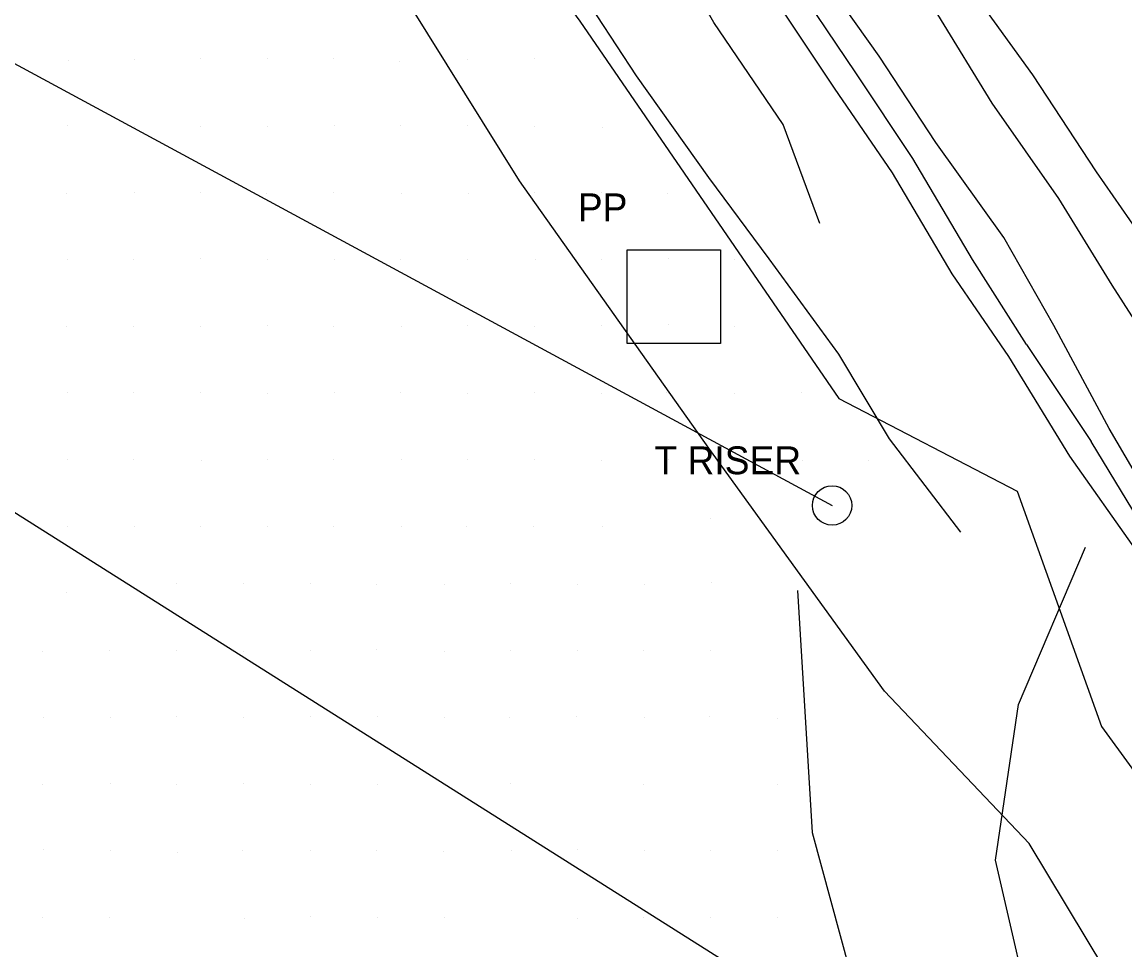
# Model space of a CAD drawing. Extents: x 1602514 to 1609837, y 863887 to 871157.
# Drawn here: x 1604592.6 to 1604840.4, y 867560.7 to 867769.2 of the extents above; entities that cross this region are included whole.
import ezdxf

# ---------------------------------------------------------------- set-up
doc = ezdxf.new("R2010")
doc.units = 0
for name, color, linetype in [('Survey-Flow line', 7, 'Continuous'), ('Survey-Ridge Lines', 7, 'Continuous'), ('Survey-Spot dirt', 7, 'Continuous'), ('Survey-Vegetation trees', 7, 'Continuous'), ('Text General Notes', 7, 'Continuous'), ('Utility-Pole', 7, 'Continuous'), ('Utility-Telephone', 7, 'Continuous')]:
    doc.layers.add(name, color=color, linetype=linetype)

msp = doc.modelspace()

# ---------------------------------------------------------------- linework, layer by layer
at = {"layer": 'Survey-Flow line'}
msp.add_line((1604818.28, 867696.73), (1604832.8, 867674.97), dxfattribs=at)
msp.add_line((1604818.28, 867696.73), (1604832.8, 867674.97), dxfattribs=at)
for points in [[(1604818.28, 867696.73), (1604806.16, 867715.81), (1604792.77, 867738.49), (1604779.99, 867757.77), (1604764.6, 867780.55), (1604750.71, 867800.58)], [(1604818.28, 867696.73), (1604806.16, 867715.81), (1604792.77, 867738.49), (1604779.99, 867757.77), (1604764.6, 867780.55), (1604750.71, 867800.58)], [(1604921.51, 867529.19), (1604914.06, 867533.2), (1604906.06, 867537.4), (1604903.35, 867541.31), (1604892.31, 867564.09), (1604882.35, 867587.62), (1604870.6, 867609.9), (1604857.3, 867633.58), (1604846.26, 867652.84), (1604832.8, 867674.97)], [(1604921.51, 867529.19), (1604914.06, 867533.2), (1604906.06, 867537.4), (1604903.35, 867541.31), (1604892.31, 867564.09), (1604882.35, 867587.62), (1604870.6, 867609.9), (1604857.3, 867633.58), (1604846.26, 867652.84), (1604832.8, 867674.97)], [(1604825.24, 867194.65), (1604821.17, 867216.57), (1604817.74, 867236.45), (1604799.75, 867259.61), (1604775.29, 867293.59), (1604776.33, 867315.88), (1604792.23, 867342.57), (1604806.9, 867375.02), (1604822.2, 867411.61), (1604827.76, 867442.51), (1604835.8, 867478.97), (1604831.81, 867504.07), (1604821.12, 867538.37), (1604811.33, 867580.91), (1604816.48, 867615.89), (1604831.53, 867651.16)], [(1604825.24, 867194.65), (1604821.17, 867216.57), (1604817.74, 867236.45), (1604799.75, 867259.61), (1604775.29, 867293.59), (1604776.33, 867315.88), (1604792.23, 867342.57), (1604806.9, 867375.02), (1604822.2, 867411.61), (1604827.76, 867442.51), (1604835.8, 867478.97), (1604831.81, 867504.07), (1604821.12, 867538.37), (1604811.33, 867580.91), (1604816.48, 867615.89), (1604831.53, 867651.16)]]:
    msp.add_lwpolyline(points, dxfattribs=at)
at = {"layer": 'Survey-Ridge Lines'}
for points in [[(1604803.53, 867654.54), (1604787.54, 867675.54), (1604776.14, 867694.56), (1604760.52, 867715.97), (1604746.92, 867734.21), (1604730.69, 867757.04), (1604717.43, 867777.35), (1604704.53, 867801.09), (1604688.27, 867817.96), (1604670.81, 867837.65), (1604656.79, 867858.81), (1604645.82, 867885.21), (1604624.86, 867905.16)], [(1604803.53, 867654.54), (1604787.54, 867675.54), (1604776.14, 867694.56), (1604760.52, 867715.97), (1604746.92, 867734.21), (1604730.69, 867757.04), (1604717.43, 867777.35), (1604704.53, 867801.09), (1604688.27, 867817.96), (1604670.81, 867837.65), (1604656.79, 867858.81), (1604645.82, 867885.21), (1604624.86, 867905.16)], [(1604771.85, 867723.88), (1604763.63, 867746.12), (1604748.04, 867769.06), (1604736.02, 867790.32), (1604718.51, 867810.68), (1604705.34, 867829.88)], [(1604771.85, 867723.88), (1604763.63, 867746.12), (1604748.04, 867769.06), (1604736.02, 867790.32), (1604718.51, 867810.68), (1604705.34, 867829.88)], [(1604906.22, 867543.32), (1604898.1, 867568.13), (1604886.72, 867590.67), (1604873.69, 867612.06), (1604860.94, 867636.07), (1604850.01, 867655.49), (1604836.9, 867677.83), (1604824.43, 867700.97), (1604813.19, 867720.78), (1604797.9, 867742.06), (1604785.17, 867761.46), (1604769.36, 867783.85), (1604755.21, 867803.72), (1604740.2, 867825.57)], [(1604906.22, 867543.32), (1604898.1, 867568.13), (1604886.72, 867590.67), (1604873.69, 867612.06), (1604860.94, 867636.07), (1604850.01, 867655.49), (1604836.9, 867677.83), (1604824.43, 867700.97), (1604813.19, 867720.78), (1604797.9, 867742.06), (1604785.17, 867761.46), (1604769.36, 867783.85), (1604755.21, 867803.72), (1604740.2, 867825.57)], [(1604900.26, 867539.16), (1604885.57, 867559.39), (1604876.38, 867583.45), (1604866.26, 867606.87), (1604853.93, 867631.28), (1604842.96, 867650.52), (1604828.06, 867671.66), (1604814.35, 867694.02), (1604801.58, 867712.56), (1604788.16, 867735.27), (1604775.15, 867754.32), (1604759.9, 867777.29), (1604746.08, 867797.34), (1604731.41, 867817.99)], [(1604900.26, 867539.16), (1604885.57, 867559.39), (1604876.38, 867583.45), (1604866.26, 867606.87), (1604853.93, 867631.28), (1604842.96, 867650.52), (1604828.06, 867671.66), (1604814.35, 867694.02), (1604801.58, 867712.56), (1604788.16, 867735.27), (1604775.15, 867754.32), (1604759.9, 867777.29), (1604746.08, 867797.34), (1604731.41, 867817.99)], [(1604901.44, 867631.43), (1604888.34, 867654.79), (1604875.92, 867673.73), (1604861.71, 867695.15), (1604847.12, 867716.62), (1604834.01, 867735.51), (1604819.72, 867757.3), (1604806.03, 867776.32)], [(1604901.44, 867631.43), (1604888.34, 867654.79), (1604875.92, 867673.73), (1604861.71, 867695.15), (1604847.12, 867716.62), (1604834.01, 867735.51), (1604819.72, 867757.3), (1604806.03, 867776.32)], [(1604935.81, 867563.97), (1604921.11, 867584.19), (1604904.08, 867602.79), (1604892.04, 867624.87), (1604879.36, 867648.66), (1604868.18, 867668.28), (1604851.65, 867688.13), (1604837.55, 867710.02), (1604825.58, 867729.54), (1604810.61, 867750.94), (1604798.36, 867770.86)], [(1604935.81, 867563.97), (1604921.11, 867584.19), (1604904.08, 867602.79), (1604892.04, 867624.87), (1604879.36, 867648.66), (1604868.18, 867668.28), (1604851.65, 867688.13), (1604837.55, 867710.02), (1604825.58, 867729.54), (1604810.61, 867750.94), (1604798.36, 867770.86)], [(1604766.88, 867641.49), (1604770.15, 867587.13), (1604782.72, 867540.86), (1604800.31, 867482.58)], [(1604766.88, 867641.49), (1604770.15, 867587.13), (1604782.72, 867540.86), (1604800.31, 867482.58)]]:
    msp.add_lwpolyline(points, dxfattribs=at)
at = {"layer": 'Survey-Spot dirt'}
for p, q in [((1604603.11, 867760.42), (1604603.11, 867760.42)), ((1604603.11, 867760.42), (1604603.11, 867760.42)), ((1604617.8, 867760.77), (1604617.8, 867760.77)), ((1604617.8, 867760.77), (1604617.8, 867760.77)), ((1604632.74, 867760.9), (1604632.74, 867760.9)), ((1604632.74, 867760.9), (1604632.74, 867760.9)), ((1604647.66, 867760.98), (1604647.66, 867760.98)), ((1604647.66, 867760.98), (1604647.66, 867760.98)), ((1604662.51, 867760.93), (1604662.51, 867760.93)), ((1604662.51, 867760.93), (1604662.51, 867760.93)), ((1604677.33, 867760.32), (1604677.33, 867760.32)), ((1604677.33, 867760.32), (1604677.33, 867760.32)), ((1604692.81, 867760.8), (1604692.81, 867760.8)), ((1604692.81, 867760.8), (1604692.81, 867760.8)), ((1604707.83, 867760.98), (1604707.83, 867760.98)), ((1604707.83, 867760.98), (1604707.83, 867760.98)), ((1604722.63, 867760.72), (1604722.63, 867760.72)), ((1604722.63, 867760.72), (1604722.63, 867760.72)), ((1604602.88, 867745.89), (1604602.88, 867745.89)), ((1604602.88, 867745.89), (1604602.88, 867745.89)), ((1604617.82, 867745.71), (1604617.82, 867745.71)), ((1604617.82, 867745.71), (1604617.82, 867745.71)), ((1604632.73, 867745.66), (1604632.73, 867745.66)), ((1604632.73, 867745.66), (1604632.73, 867745.66)), ((1604647.68, 867745.7), (1604647.68, 867745.7)), ((1604647.68, 867745.7), (1604647.68, 867745.7)), ((1604662.78, 867745.89), (1604662.78, 867745.89)), ((1604662.78, 867745.89), (1604662.78, 867745.89)), ((1604677.63, 867745.83), (1604677.63, 867745.83)), ((1604677.63, 867745.83), (1604677.63, 867745.83)), ((1604692.65, 867745.84), (1604692.65, 867745.84)), ((1604692.65, 867745.84), (1604692.65, 867745.84)), ((1604707.76, 867745.78), (1604707.76, 867745.78)), ((1604707.76, 867745.78), (1604707.76, 867745.78)), ((1604723.03, 867745.54), (1604723.03, 867745.54)), ((1604723.03, 867745.54), (1604723.03, 867745.54)), ((1604602.7, 867730.75), (1604602.7, 867730.75)), ((1604602.7, 867730.75), (1604602.7, 867730.75)), ((1604617.85, 867730.94), (1604617.85, 867730.94)), ((1604617.85, 867730.94), (1604617.85, 867730.94)), ((1604632.77, 867730.91), (1604632.77, 867730.91)), ((1604632.77, 867730.91), (1604632.77, 867730.91)), ((1604647.52, 867730.57), (1604647.52, 867730.57)), ((1604647.52, 867730.57), (1604647.52, 867730.57)), ((1604662.71, 867730.97), (1604662.71, 867730.97)), ((1604662.71, 867730.97), (1604662.71, 867730.97)), ((1604677.81, 867730.73), (1604677.81, 867730.73)), ((1604677.81, 867730.73), (1604677.81, 867730.73)), ((1604692.93, 867730.67), (1604692.93, 867730.67)), ((1604692.93, 867730.67), (1604692.93, 867730.67)), ((1604707.71, 867730.88), (1604707.71, 867730.88)), ((1604707.71, 867730.88), (1604707.71, 867730.88)), ((1604722.89, 867730.85), (1604722.89, 867730.85)), ((1604722.89, 867730.85), (1604722.89, 867730.85)), ((1604737.7, 867730.74), (1604737.7, 867730.74)), ((1604737.7, 867730.74), (1604737.7, 867730.74)), ((1604602.85, 867715.72), (1604602.85, 867715.72)), ((1604602.85, 867715.72), (1604602.85, 867715.72)), ((1604617.72, 867715.77), (1604617.72, 867715.77)), ((1604617.72, 867715.77), (1604617.72, 867715.77)), ((1604632.66, 867715.95), (1604632.66, 867715.95)), ((1604632.66, 867715.95), (1604632.66, 867715.95)), ((1604647.67, 867715.82), (1604647.67, 867715.82)), ((1604647.67, 867715.82), (1604647.67, 867715.82)), ((1604662.91, 867715.73), (1604662.91, 867715.73)), ((1604662.91, 867715.73), (1604662.91, 867715.73)), ((1604677.65, 867715.92), (1604677.65, 867715.92)), ((1604677.65, 867715.92), (1604677.65, 867715.92)), ((1604692.8, 867715.8), (1604692.8, 867715.8)), ((1604692.8, 867715.8), (1604692.8, 867715.8)), ((1604708.03, 867715.74), (1604708.03, 867715.74)), ((1604708.03, 867715.74), (1604708.03, 867715.74)), ((1604722.81, 867715.84), (1604722.81, 867715.84)), ((1604722.81, 867715.84), (1604722.81, 867715.84)), ((1604737.76, 867715.96), (1604737.76, 867715.96)), ((1604737.76, 867715.96), (1604737.76, 867715.96)), ((1604752.78, 867715.79), (1604752.78, 867715.79)), ((1604752.78, 867715.79), (1604752.78, 867715.79)), ((1604602.63, 867700.85), (1604602.63, 867700.85)), ((1604602.63, 867700.85), (1604602.63, 867700.85)), ((1604617.69, 867700.84), (1604617.69, 867700.84)), ((1604617.69, 867700.84), (1604617.69, 867700.84)), ((1604632.71, 867700.74), (1604632.71, 867700.74)), ((1604632.71, 867700.74), (1604632.71, 867700.74)), ((1604647.68, 867700.91), (1604647.68, 867700.91)), ((1604647.68, 867700.91), (1604647.68, 867700.91)), ((1604662.65, 867700.77), (1604662.65, 867700.77)), ((1604662.65, 867700.77), (1604662.65, 867700.77)), ((1604677.92, 867700.68), (1604677.92, 867700.68)), ((1604677.92, 867700.68), (1604677.92, 867700.68)), ((1604692.7, 867700.88), (1604692.7, 867700.88)), ((1604692.7, 867700.88), (1604692.7, 867700.88)), ((1604707.76, 867700.72), (1604707.76, 867700.72)), ((1604707.76, 867700.72), (1604707.76, 867700.72)), ((1604722.79, 867700.95), (1604722.79, 867700.95)), ((1604722.79, 867700.95), (1604722.79, 867700.95)), ((1604737.86, 867701.18), (1604737.86, 867701.18)), ((1604737.86, 867701.18), (1604737.86, 867701.18)), ((1604752.65, 867700.71), (1604752.65, 867700.71)), ((1604752.65, 867700.71), (1604752.65, 867700.71)), ((1604602.79, 867685.91), (1604602.79, 867685.91)), ((1604602.79, 867685.91), (1604602.79, 867685.91)), ((1604617.65, 867685.83), (1604617.65, 867685.83)), ((1604617.65, 867685.83), (1604617.65, 867685.83)), ((1604632.62, 867685.87), (1604632.62, 867685.87)), ((1604632.62, 867685.87), (1604632.62, 867685.87)), ((1604647.72, 867685.8), (1604647.72, 867685.8)), ((1604647.72, 867685.8), (1604647.72, 867685.8)), ((1604662.89, 867685.87), (1604662.89, 867685.87)), ((1604662.89, 867685.87), (1604662.89, 867685.87)), ((1604677.69, 867685.88), (1604677.69, 867685.88)), ((1604677.69, 867685.88), (1604677.69, 867685.88)), ((1604692.79, 867685.81), (1604692.79, 867685.81)), ((1604692.79, 867685.81), (1604692.79, 867685.81)), ((1604707.68, 867685.85), (1604707.68, 867685.85)), ((1604707.68, 867685.85), (1604707.68, 867685.85)), ((1604722.87, 867685.71), (1604722.87, 867685.71)), ((1604722.87, 867685.71), (1604722.87, 867685.71)), ((1604737.5, 867685.9), (1604737.5, 867685.9)), ((1604737.5, 867685.9), (1604737.5, 867685.9)), ((1604752.78, 867685.81), (1604752.78, 867685.81)), ((1604752.78, 867685.81), (1604752.78, 867685.81)), ((1604767.71, 867685.86), (1604767.71, 867685.86)), ((1604767.71, 867685.86), (1604767.71, 867685.86)), ((1604602.74, 867670.79), (1604602.74, 867670.79)), ((1604602.74, 867670.79), (1604602.74, 867670.79)), ((1604617.73, 867670.91), (1604617.73, 867670.91)), ((1604617.73, 867670.91), (1604617.73, 867670.91)), ((1604632.89, 867670.74), (1604632.89, 867670.74)), ((1604632.89, 867670.74), (1604632.89, 867670.74)), ((1604647.71, 867670.88), (1604647.71, 867670.88)), ((1604647.71, 867670.88), (1604647.71, 867670.88)), ((1604662.71, 867670.86), (1604662.71, 867670.86)), ((1604662.71, 867670.86), (1604662.71, 867670.86)), ((1604677.78, 867670.98), (1604677.78, 867670.98)), ((1604677.78, 867670.98), (1604677.78, 867670.98)), ((1604692.75, 867670.95), (1604692.75, 867670.95)), ((1604692.75, 867670.95), (1604692.75, 867670.95)), ((1604707.7, 867670.91), (1604707.7, 867670.91)), ((1604707.7, 867670.91), (1604707.7, 867670.91)), ((1604722.82, 867670.74), (1604722.82, 867670.74)), ((1604722.82, 867670.74), (1604722.82, 867670.74)), ((1604737.91, 867670.85), (1604737.91, 867670.85)), ((1604737.91, 867670.85), (1604737.91, 867670.85)), ((1604752.69, 867670.89), (1604752.69, 867670.89)), ((1604752.69, 867670.89), (1604752.69, 867670.89)), ((1604767.89, 867670.77), (1604767.89, 867670.77)), ((1604767.89, 867670.77), (1604767.89, 867670.77)), ((1604782.75, 867670.76), (1604782.75, 867670.76)), ((1604782.75, 867670.76), (1604782.75, 867670.76)), ((1604602.81, 867655.74), (1604602.81, 867655.74)), ((1604602.81, 867655.74), (1604602.81, 867655.74)), ((1604617.87, 867655.75), (1604617.87, 867655.75)), ((1604617.87, 867655.75), (1604617.87, 867655.75)), ((1604632.73, 867655.84), (1604632.73, 867655.84)), ((1604632.73, 867655.84), (1604632.73, 867655.84)), ((1604647.72, 867655.86), (1604647.72, 867655.86)), ((1604647.72, 867655.86), (1604647.72, 867655.86)), ((1604662.69, 867655.84), (1604662.69, 867655.84)), ((1604662.69, 867655.84), (1604662.69, 867655.84)), ((1604677.83, 867655.92), (1604677.83, 867655.92)), ((1604677.83, 867655.92), (1604677.83, 867655.92)), ((1604692.58, 867655.84), (1604692.58, 867655.84)), ((1604692.58, 867655.84), (1604692.58, 867655.84)), ((1604707.64, 867655.77), (1604707.64, 867655.77)), ((1604707.64, 867655.77), (1604707.64, 867655.77)), ((1604723.01, 867655.94), (1604723.01, 867655.94)), ((1604723.01, 867655.94), (1604723.01, 867655.94)), ((1604747.33, 867657.74), (1604747.33, 867657.74)), ((1604747.33, 867657.74), (1604747.33, 867657.74)), ((1604747.52, 867643.21), (1604747.52, 867643.21)), ((1604747.52, 867643.21), (1604747.52, 867643.21)), ((1604602.67, 867641.04), (1604602.67, 867641.04)), ((1604602.67, 867641.04), (1604602.67, 867641.04)), ((1604627.34, 867642.97), (1604627.34, 867642.97)), ((1604627.34, 867642.97), (1604627.34, 867642.97)), ((1604642.28, 867643.05), (1604642.28, 867643.05)), ((1604642.28, 867643.05), (1604642.28, 867643.05)), ((1604657.36, 867642.98), (1604657.36, 867642.98)), ((1604657.36, 867642.98), (1604657.36, 867642.98)), ((1604672.17, 867642.92), (1604672.17, 867642.92)), ((1604672.17, 867642.92), (1604672.17, 867642.92)), ((1604687.57, 867642.88), (1604687.57, 867642.88)), ((1604687.57, 867642.88), (1604687.57, 867642.88)), ((1604702.29, 867643.03), (1604702.29, 867643.03)), ((1604702.29, 867643.03), (1604702.29, 867643.03)), ((1604717.32, 867642.86), (1604717.32, 867642.86)), ((1604717.32, 867642.86), (1604717.32, 867642.86)), ((1604732.44, 867642.87), (1604732.44, 867642.87)), ((1604732.44, 867642.87), (1604732.44, 867642.87)), ((1604597.32, 867627.81), (1604597.32, 867627.81)), ((1604597.32, 867627.81), (1604597.32, 867627.81)), ((1604612.36, 867627.96), (1604612.36, 867627.96)), ((1604612.36, 867627.96), (1604612.36, 867627.96)), ((1604627.37, 867628.08), (1604627.37, 867628.08)), ((1604627.37, 867628.08), (1604627.37, 867628.08)), ((1604642.36, 867627.76), (1604642.36, 867627.76)), ((1604642.36, 867627.76), (1604642.36, 867627.76)), ((1604657.36, 867628), (1604657.36, 867628)), ((1604657.36, 867628), (1604657.36, 867628)), ((1604672.34, 867628.12), (1604672.34, 867628.12)), ((1604672.34, 867628.12), (1604672.34, 867628.12)), ((1604687.47, 867627.86), (1604687.47, 867627.86)), ((1604687.47, 867627.86), (1604687.47, 867627.86)), ((1604702.35, 867628), (1604702.35, 867628)), ((1604702.35, 867628), (1604702.35, 867628)), ((1604717.31, 867628.04), (1604717.31, 867628.04)), ((1604717.31, 867628.04), (1604717.31, 867628.04)), ((1604732.33, 867627.93), (1604732.33, 867627.93)), ((1604732.33, 867627.93), (1604732.33, 867627.93)), ((1604747.22, 867627.91), (1604747.22, 867627.91)), ((1604747.22, 867627.91), (1604747.22, 867627.91)), ((1604597.42, 867613.04), (1604597.42, 867613.04)), ((1604597.42, 867613.04), (1604597.42, 867613.04)), ((1604612.52, 867612.88), (1604612.52, 867612.88)), ((1604612.52, 867612.88), (1604612.52, 867612.88)), ((1604627.31, 867613.09), (1604627.31, 867613.09)), ((1604627.31, 867613.09), (1604627.31, 867613.09)), ((1604642.34, 867613.01), (1604642.34, 867613.01)), ((1604642.34, 867613.01), (1604642.34, 867613.01)), ((1604657.46, 867613.08), (1604657.46, 867613.08)), ((1604657.46, 867613.08), (1604657.46, 867613.08)), ((1604672.57, 867613.12), (1604672.57, 867613.12)), ((1604672.57, 867613.12), (1604672.57, 867613.12)), ((1604687.45, 867612.93), (1604687.45, 867612.93)), ((1604687.45, 867612.93), (1604687.45, 867612.93)), ((1604702.1, 867612.97), (1604702.1, 867612.97)), ((1604702.1, 867612.97), (1604702.1, 867612.97)), ((1604717.28, 867613.08), (1604717.28, 867613.08)), ((1604717.28, 867613.08), (1604717.28, 867613.08)), ((1604732.4, 867613), (1604732.4, 867613)), ((1604732.4, 867613), (1604732.4, 867613)), ((1604747.16, 867613.08), (1604747.16, 867613.08)), ((1604747.16, 867613.08), (1604747.16, 867613.08)), ((1604762.3, 867612.79), (1604762.3, 867612.79)), ((1604762.3, 867612.79), (1604762.3, 867612.79)), ((1604597.3, 867597.94), (1604597.3, 867597.94)), ((1604597.3, 867597.94), (1604597.3, 867597.94)), ((1604612.42, 867598.05), (1604612.42, 867598.05)), ((1604612.42, 867598.05), (1604612.42, 867598.05)), ((1604627.42, 867597.96), (1604627.42, 867597.96)), ((1604627.42, 867597.96), (1604627.42, 867597.96)), ((1604642.29, 867598.08), (1604642.29, 867598.08)), ((1604642.29, 867598.08), (1604642.29, 867598.08)), ((1604657.41, 867597.98), (1604657.41, 867597.98)), ((1604657.41, 867597.98), (1604657.41, 867597.98)), ((1604672.5, 867597.93), (1604672.5, 867597.93)), ((1604672.5, 867597.93), (1604672.5, 867597.93)), ((1604687.37, 867598.12), (1604687.37, 867598.12)), ((1604687.37, 867598.12), (1604687.37, 867598.12)), ((1604702.37, 867598.04), (1604702.37, 867598.04)), ((1604702.37, 867598.04), (1604702.37, 867598.04)), ((1604732.21, 867597.96), (1604732.21, 867597.96)), ((1604732.21, 867597.96), (1604732.21, 867597.96)), ((1604762.43, 867597.88), (1604762.43, 867597.88)), ((1604762.43, 867597.88), (1604762.43, 867597.88)), ((1604597.43, 867583.26), (1604597.43, 867583.26)), ((1604597.43, 867583.26), (1604597.43, 867583.26)), ((1604612.45, 867583.08), (1604612.45, 867583.08)), ((1604612.45, 867583.08), (1604612.45, 867583.08)), ((1604627.54, 867582.65), (1604627.54, 867582.65)), ((1604627.54, 867582.65), (1604627.54, 867582.65)), ((1604642.2, 867583.03), (1604642.2, 867583.03)), ((1604642.2, 867583.03), (1604642.2, 867583.03)), ((1604657.36, 867583.07), (1604657.36, 867583.07)), ((1604657.36, 867583.07), (1604657.36, 867583.07)), ((1604672.28, 867583.16), (1604672.28, 867583.16)), ((1604672.28, 867583.16), (1604672.28, 867583.16)), ((1604687.37, 867582.83), (1604687.37, 867582.83)), ((1604687.37, 867582.83), (1604687.37, 867582.83)), ((1604702.52, 867583.14), (1604702.52, 867583.14)), ((1604702.52, 867583.14), (1604702.52, 867583.14)), ((1604717.51, 867583.18), (1604717.51, 867583.18)), ((1604717.51, 867583.18), (1604717.51, 867583.18)), ((1604732.4, 867583.01), (1604732.4, 867583.01)), ((1604732.4, 867583.01), (1604732.4, 867583.01)), ((1604747.27, 867583.05), (1604747.27, 867583.05)), ((1604747.27, 867583.05), (1604747.27, 867583.05)), ((1604762.35, 867583.09), (1604762.35, 867583.09)), ((1604762.35, 867583.09), (1604762.35, 867583.09)), ((1604597.26, 867567.98), (1604597.26, 867567.98)), ((1604597.26, 867567.98), (1604597.26, 867567.98)), ((1604612.28, 867568.04), (1604612.28, 867568.04)), ((1604612.28, 867568.04), (1604612.28, 867568.04)), ((1604642.52, 867567.73), (1604642.52, 867567.73)), ((1604642.52, 867567.73), (1604642.52, 867567.73)), ((1604657.42, 867568.16), (1604657.42, 867568.16)), ((1604657.42, 867568.16), (1604657.42, 867568.16)), ((1604672.56, 867568.07), (1604672.56, 867568.07)), ((1604672.56, 867568.07), (1604672.56, 867568.07)), ((1604687.49, 867568.07), (1604687.49, 867568.07)), ((1604687.49, 867568.07), (1604687.49, 867568.07)), ((1604717.33, 867567.79), (1604717.33, 867567.79)), ((1604717.33, 867567.79), (1604717.33, 867567.79)), ((1604732.27, 867567.95), (1604732.27, 867567.95)), ((1604732.27, 867567.95), (1604732.27, 867567.95)), ((1604747.27, 867568.03), (1604747.27, 867568.03)), ((1604747.27, 867568.03), (1604747.27, 867568.03)), ((1604762.35, 867567.95), (1604762.35, 867567.95)), ((1604762.35, 867567.95), (1604762.35, 867567.95))]:
    msp.add_line(p, q, dxfattribs=at)
at = {"layer": 'Survey-Vegetation trees'}
for points in [[(1604465.35, 868345.01), (1604480.44, 868314.98), (1604495.45, 868291.7), (1604491.72, 868255.78), (1604521.78, 868176.35), (1604546.15, 868113.56), (1604572.9, 868110.61), (1604579.39, 868059.4), (1604588.72, 868021.51), (1604589.21, 867983.05), (1604619.52, 867916.56), (1604677.17, 867824.91), (1604717.98, 867769.39), (1604776.16, 867684.57), (1604816.24, 867663.79), (1604835.18, 867610.93), (1604877.81, 867552.25), (1604900.87, 867512.26)], [(1604465.35, 868345.01), (1604480.44, 868314.98), (1604495.45, 868291.7), (1604491.72, 868255.78), (1604521.78, 868176.35), (1604546.15, 868113.56), (1604572.9, 868110.61), (1604579.39, 868059.4), (1604588.72, 868021.51), (1604589.21, 867983.05), (1604619.52, 867916.56), (1604677.17, 867824.91), (1604717.98, 867769.39), (1604776.16, 867684.57), (1604816.24, 867663.79), (1604835.18, 867610.93), (1604877.81, 867552.25), (1604900.87, 867512.26)], [(1604876.85, 867493.59), (1604857.09, 867521.24), (1604818.92, 867584.6), (1604786.39, 867618.88), (1604746.95, 867673.42), (1604704.4, 867733.5), (1604646.98, 867825.65), (1604600.64, 867890.1), (1604575.99, 867935.59), (1604550.67, 867991.09), (1604524.52, 868064.86), (1604498.87, 868136.02), (1604456.32, 868251.5), (1604438.4, 868315.53)], [(1604876.85, 867493.59), (1604857.09, 867521.24), (1604818.92, 867584.6), (1604786.39, 867618.88), (1604746.95, 867673.42), (1604704.4, 867733.5), (1604646.98, 867825.65), (1604600.64, 867890.1), (1604575.99, 867935.59), (1604550.67, 867991.09), (1604524.52, 868064.86), (1604498.87, 868136.02), (1604456.32, 868251.5), (1604438.4, 868315.53)]]:
    msp.add_lwpolyline(points, dxfattribs=at)
at = {"layer": 'Text General Notes'}
for p, q in [((1604890.89, 867469.5), (1603488.83, 868354.84)), ((1603488.83, 868354.84), (1604774.62, 867660.57)), ((1604890.89, 867469.5), (1603488.83, 868354.84)), ((1603488.83, 868354.84), (1604774.62, 867660.57))]:
    msp.add_line(p, q, dxfattribs=at)
at = {"layer": 'Utility-Pole'}
msp.add_lwpolyline([(1604728.55, 867717.95), (1604749.55, 867717.95), (1604749.55, 867696.94), (1604728.55, 867696.94)], close=True, dxfattribs=at)
msp.add_lwpolyline([(1604728.55, 867717.95), (1604749.55, 867717.95), (1604749.55, 867696.94), (1604728.55, 867696.94)], close=True, dxfattribs=at)
at = {"layer": 'Utility-Telephone'}
msp.add_circle((1604774.62, 867660.57), 4.42, dxfattribs=at)
msp.add_circle((1604774.62, 867660.57), 4.42, dxfattribs=at)

# ---------------------------------------------------------------- texts
at = {"layer": 'Utility-Pole'}
msp.add_text('PP', height=6.251, dxfattribs=at).set_placement((1604717.49, 867724.41))
msp.add_text('PP', height=6.251, dxfattribs=at).set_placement((1604717.49, 867724.41))
at = {"layer": 'Utility-Telephone'}
msp.add_text('T RISER', height=6.251, dxfattribs=at).set_placement((1604734.7, 867667.58))
msp.add_text('T RISER', height=6.251, dxfattribs=at).set_placement((1604734.7, 867667.58))

doc.saveas('drawing.dxf')
